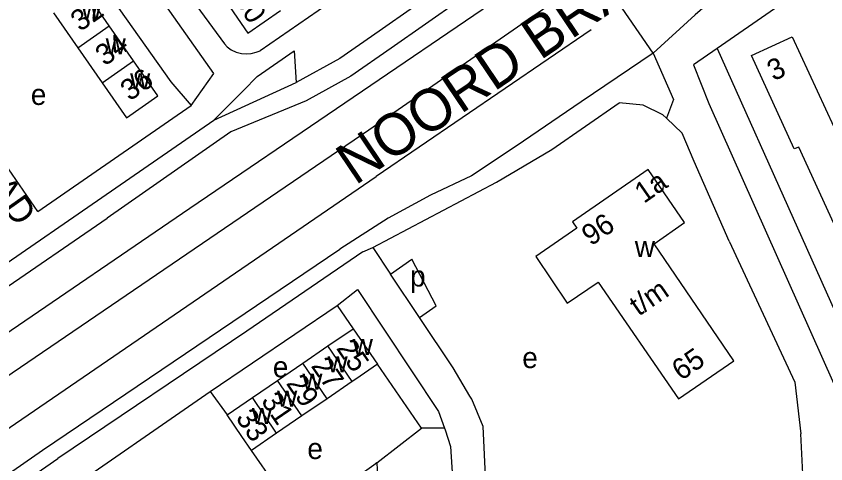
# Model space of a CAD drawing. Extents: x 157569 to 159501, y 382907 to 384670.
# Drawn here: x 158580.7 to 158735.9, y 383618.6 to 383704.3 of the extents above; entities that cross this region are included whole.
import ezdxf

# ---------------------------------------------------------------- set-up
doc = ezdxf.new("R2010")
doc.units = 0
for name, color, linetype in [('BLT_Basislijn', 7, 'Continuous'), ('BLT_Bebouwing', 7, 'Continuous'), ('BLT_Centroide', 7, 'Continuous'), ('BLT_Huisnummer', 7, 'Continuous'), ('BLT_Huisnummer_ tussenligend', 7, 'Continuous'), ('BLT_Huisnummer_reeks', 7, 'Continuous'), ('BLT_Huisnummer_zonder_bebouwing', 7, 'Continuous'), ('BLT_Onderverdeling_panden', 7, 'Continuous'), ('BLT_Straatnaam', 7, 'Continuous'), ('BLT_Straatnaam_hoofdweg', 7, 'Continuous'), ('BLT_Vlakafsluiter', 7, 'Continuous')]:
    doc.layers.add(name, color=color, linetype=linetype)

msp = doc.modelspace()

# ---------------------------------------------------------------- linework, layer by layer
at = {"layer": 'BLT_Basislijn'}
for p, q in [((158672.16, 383728.53), (158627.43, 383697.68)), ((158613.95, 383667.53), (158673.97, 383708.32)), ((158648.25, 383682.56), (158686.1, 383708.74)), ((158584.86, 383666.93), (158560.92, 383701.5)), ((158690.88, 383701.66), (158649.69, 383673.59)), ((158626.85, 383692.74), (158633.97, 383697.64)), ((158633.97, 383697.64), (158634.36, 383691.62)), ((158618.54, 383684.37), (158634.36, 383691.62)), ((158584.86, 383666.93), (158614.21, 383687.19)), ((158499.37, 383581.17), (158648.25, 383682.56)), ((158499.73, 383571.06), (158649.69, 383673.59)), ((158500.28, 383602.92), (158597.09, 383669.61)), ((158500, 383589.9), (158613.95, 383667.53)), ((158500.28, 383598.56), (158598.13, 383665.66)), ((158642.19, 383648.91), (158646.08, 383651.97)), ((158642.19, 383648.91), (158645.28, 383644.47)), ((158658.34, 383625.46), (158649.92, 383637.67)), ((158617.88, 383632.46), (158621.12, 383627.99)), ((158649.82, 383618.8), (158658.34, 383625.46)), ((158662.79, 383625.43), (158658.34, 383625.46)), ((158670.74, 383613.8), (158670.21, 383625.73)), ((158731.42, 383616.69), (158731.04, 383624.35)), ((158649.82, 383618.8), (158650.22, 383611.32))]:
    msp.add_line(p, q, dxfattribs=at)
for points in [[(158760.76, 383740.58), (158743.71, 383729.14), (158726.02, 383716.86), (158719.15, 383711.86), (158710.83, 383704.58), (158702.74, 383697.25)], [(158614.21, 383687.19), (158618.56, 383693.32), (158596.04, 383725.3)], [(158589.64, 383720.99), (158610.35, 383691.71), (158614.21, 383687.19)], [(158609.6, 383714.52), (158613.71, 383708.45), (158620.59, 383698.98)], [(158737.83, 383713.93), (158715.02, 383698.14)], [(158663.41, 383710.7), (158650.27, 383701.46), (158642.71, 383696.23), (158634.36, 383691.62)], [(158665.71, 383707.43), (158652.56, 383698.18), (158644.82, 383692.82), (158636.29, 383688.11)], [(158620.59, 383698.98), (158621.14, 383698.42), (158621.9, 383697.89), (158622.85, 383697.44), (158623.86, 383697.13), (158624.81, 383697.08), (158625.73, 383697.16), (158626.71, 383697.39), (158627.43, 383697.68)], [(158702.74, 383697.25), (158688.99, 383687.93), (158676.51, 383679.39), (158667.98, 383673.77), (158660.07, 383670.03), (158651.96, 383665.66), (158642.75, 383659.69)], [(158702.74, 383697.25), (158706.67, 383688.34), (158705.31, 383684.75)], [(158715.02, 383698.14), (158710.51, 383695.02)], [(158715.02, 383698.14), (158745.8, 383629.49), (158752.9, 383630.63)], [(158710.51, 383695.02), (158713.43, 383687.6), (158741.59, 383624.49)], [(158618.54, 383684.37), (158624.23, 383690.06), (158626.85, 383692.74)], [(158636.29, 383688.11), (158621.85, 383682.16), (158598.13, 383665.66)], [(158649.05, 383660.04), (158672.76, 383672.52), (158683.37, 383678.77), (158696.27, 383687.72)], [(158705.31, 383684.75), (158704.59, 383685.43), (158700.85, 383687.3), (158696.27, 383687.72)], [(158597.09, 383669.61), (158618.54, 383684.37)], [(158717.35, 383661.22), (158710.63, 383676.48), (158708.34, 383681.89), (158705.31, 383684.75)], [(158647.15, 383659.21), (158649.05, 383660.04)], [(158649.05, 383660.04), (158652.41, 383654.94)], [(158717.35, 383661.22), (158729.94, 383634.26), (158731.04, 383624.35)], [(158499.73, 383563.08), (158544.38, 383592.54), (158585.75, 383621.2), (158642.75, 383659.69)], [(158647.15, 383659.21), (158624.89, 383644.01), (158588.65, 383619.66)], [(158652.41, 383654.94), (158656.53, 383657.78)], [(158661.2, 383648.86), (158656.53, 383657.78)], [(158657.98, 383646.63), (158652.41, 383654.94)], [(158646.08, 383651.97), (158661.62, 383628.66), (158662.79, 383625.43)], [(158617.88, 383632.46), (158642.19, 383648.91)], [(158657.98, 383646.63), (158661.2, 383648.86)], [(158667.64, 383631.58), (158664.43, 383637.02), (158657.98, 383646.63)], [(158588.18, 383611.93), (158617.88, 383632.46)], [(158670.21, 383625.73), (158668.01, 383630.96), (158667.64, 383631.58)], [(158662.79, 383625.43), (158662.89, 383625.15), (158663.95, 383621.91), (158664.56, 383612.06)], [(158649.82, 383618.8), (158649.26, 383618.36), (158634.86, 383608.17), (158625.77, 383621.18)], [(158500, 383558.78), (158536.43, 383583.45), (158588.65, 383619.66)]]:
    msp.add_lwpolyline(points, dxfattribs=at)
at = {"layer": 'BLT_Bebouwing'}
for p, q in [((158598.52, 383702.45), (158593.85, 383709.15)), ((158587.84, 383704.96), (158592.5, 383698.26)), ((158603.18, 383695.74), (158598.52, 383702.45)), ((158721.61, 383696.8), (158729.41, 383700.35)), ((158729.41, 383700.35), (158737.42, 383683.13)), ((158592.5, 383698.26), (158597.17, 383691.55)), ((158729.78, 383678.88), (158721.61, 383696.8)), ((158730.69, 383679.26), (158729.78, 383678.88)), ((158752.9, 383630.63), (158730.69, 383679.26)), ((158640.45, 383641.18), (158645.28, 383644.47)), ((158645.28, 383644.47), (158649.92, 383637.67)), ((158635.62, 383637.88), (158640.45, 383641.18)), ((158630.79, 383634.58), (158635.62, 383637.88)), ((158625.95, 383631.28), (158630.79, 383634.58)), ((158645.09, 383634.37), (158640.26, 383631.07)), ((158621.12, 383627.99), (158625.95, 383631.28)), ((158640.26, 383631.07), (158635.43, 383627.78)), ((158635.43, 383627.78), (158630.6, 383624.48)), ((158630.6, 383624.48), (158625.77, 383621.18))]:
    msp.add_line(p, q, dxfattribs=at)
for points in [[(158613.95, 383717.27), (158625.08, 383701.05), (158631.36, 383705.36)], [(158597.17, 383691.55), (158601.84, 383684.86), (158607.85, 383689.05), (158603.18, 383695.74)], [(158680.27, 383658.32), (158686.29, 383649.37), (158692.25, 383653.4), (158707.61, 383631.03), (158718.23, 383638.31), (158702.94, 383660.72), (158708.78, 383664.8), (158701.84, 383674.93), (158687.29, 383664.95), (158688.13, 383663.72), (158680.27, 383658.32)], [(158649.92, 383637.67), (158645.8, 383634.85), (158645.09, 383634.37)], [(158625.77, 383621.18), (158623.94, 383623.86), (158621.12, 383627.99)]]:
    msp.add_lwpolyline(points, dxfattribs=at)
at = {"layer": 'BLT_Onderverdeling_panden'}
for p, q in [((158592.5, 383698.26), (158598.52, 383702.45)), ((158597.17, 383691.55), (158603.18, 383695.74)), ((158645.09, 383634.37), (158640.45, 383641.18)), ((158640.26, 383631.07), (158635.62, 383637.88)), ((158635.43, 383627.78), (158630.79, 383634.58)), ((158630.6, 383624.48), (158625.95, 383631.28))]:
    msp.add_line(p, q, dxfattribs=at)
at = {"layer": 'BLT_Vlakafsluiter'}
msp.add_line((158702.74, 383697.25), (158688.32, 383718.17), dxfattribs=at)

# ---------------------------------------------------------------- texts
at = {"layer": 'BLT_Centroide'}
for s, p in [('w', (158593.17, 383703.7)), ('w', (158597.84, 383697)), ('w', (158602.52, 383690.3)), ('e', (158583.5, 383687.31)), ('w', (158699.25, 383658.19)), ('p', (158656.18, 383652.55)), ('w', (158645.19, 383639.42)), ('e', (158677.68, 383636.94)), ('e', (158629.88, 383635.17)), ('w', (158640.36, 383636.12)), ('w', (158635.53, 383632.83)), ('w', (158630.69, 383629.53)), ('w', (158625.86, 383626.23)), ('e', (158636.49, 383619.53))]:
    msp.add_text(s, height=4, dxfattribs=at).set_placement(p)
at = {"layer": 'BLT_Huisnummer'}
for s, rotation, p in [('36', 34.8652, (158602.46, 383687.94)), ('25', 304.313, (158641.92, 383640.74)), ('29', 304.313, (158632.31, 383634.01)), ('33', 304.313, (158622.64, 383627.4))]:
    msp.add_text(s, height=4, rotation=rotation, dxfattribs=at).set_placement(p)
at = {"layer": 'BLT_Huisnummer_ tussenligend'}
for s, rotation, p in [('32', 34.8633, (158592.93, 383701.24)), ('34', 34.8633, (158597.66, 383694.65)), ('27', 304.313, (158637.08, 383637.35)), ('31', 304.313, (158627.5, 383630.65))]:
    msp.add_text(s, height=4, rotation=rotation, dxfattribs=at).set_placement(p)
at = {"layer": 'BLT_Huisnummer_reeks'}
for s, rotation, p in [('80', 304.3891, (158622.2, 383707.46)), ('1a', 34.957, (158700.99, 383668.34)), ('96', 34.4543, (158690.83, 383660.2)), ('t/m', 34.4543, (158699.99, 383646.76)), ('65', 34.4543, (158708.11, 383634.41))]:
    msp.add_text(s, height=4, rotation=rotation, dxfattribs=at).set_placement(p)
at = {"layer": 'BLT_Huisnummer_zonder_bebouwing'}
msp.add_text('3', height=4, rotation=26.4365, dxfattribs=at).set_placement((158725.87, 383691.8))
at = {"layer": 'BLT_Straatnaam'}
msp.add_text('SIMONSPAD', height=5, rotation=305.2167, dxfattribs=at).set_placement((158557.65, 383696.58))
at = {"layer": 'BLT_Straatnaam_hoofdweg'}
msp.add_text('NOORD BRABANTLAAN', height=8, rotation=34.0328, dxfattribs=at).set_placement((158645.65, 383671.81))

doc.saveas('drawing.dxf')
